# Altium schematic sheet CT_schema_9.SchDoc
size 147 x 119 mm
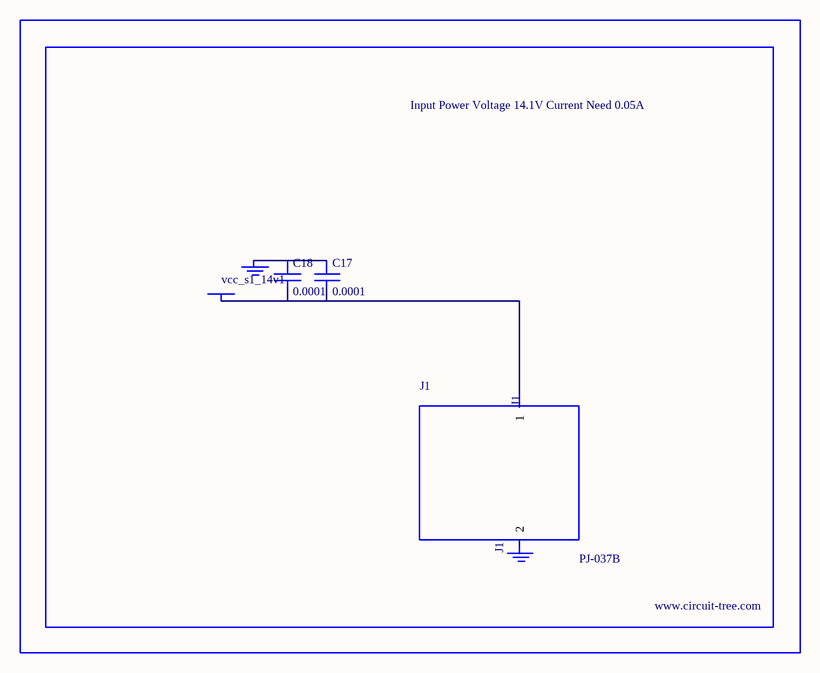
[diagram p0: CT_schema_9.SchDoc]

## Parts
BORDER8  (no value)
C17  0.0001  [EXV-9H]
C18  0.0001  [EXV-9H]
GND_INSTANCE_8_0  (no value)
GND_INSTANCE_8_1  (no value)
J1  PJ-037B  [PJ-037B_PACKAGE]
POWER_INSTANCE_8_0  vcc_s1_14v1

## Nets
NetC17_1: C17.1 C18.1 GND_INSTANCE_8_0.0(GND)
NetC17_2: C17.2 C18.2 J1.1 POWER_INSTANCE_8_0.0(PWR)

Not connected (* = marked no-connect by the designer): GND_INSTANCE_8_1 0(GND); J1 2

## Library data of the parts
BORDER8 = BORDER_PAGE8
C17 C18 = EDK107M035A9HAA
GND_INSTANCE_8_0 GND_INSTANCE_8_1 = GND
POWER_INSTANCE_8_0 = PWR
